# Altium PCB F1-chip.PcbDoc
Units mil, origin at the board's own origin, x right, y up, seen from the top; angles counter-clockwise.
Board outline 1181.1 x 1133.14 mil, 4 copper layers (Top Layer, GND, Signal & VCC, Bottom Layer), stack 23.756 mil thick; 61 components, 75 nets, 303 pads, 84 vias.
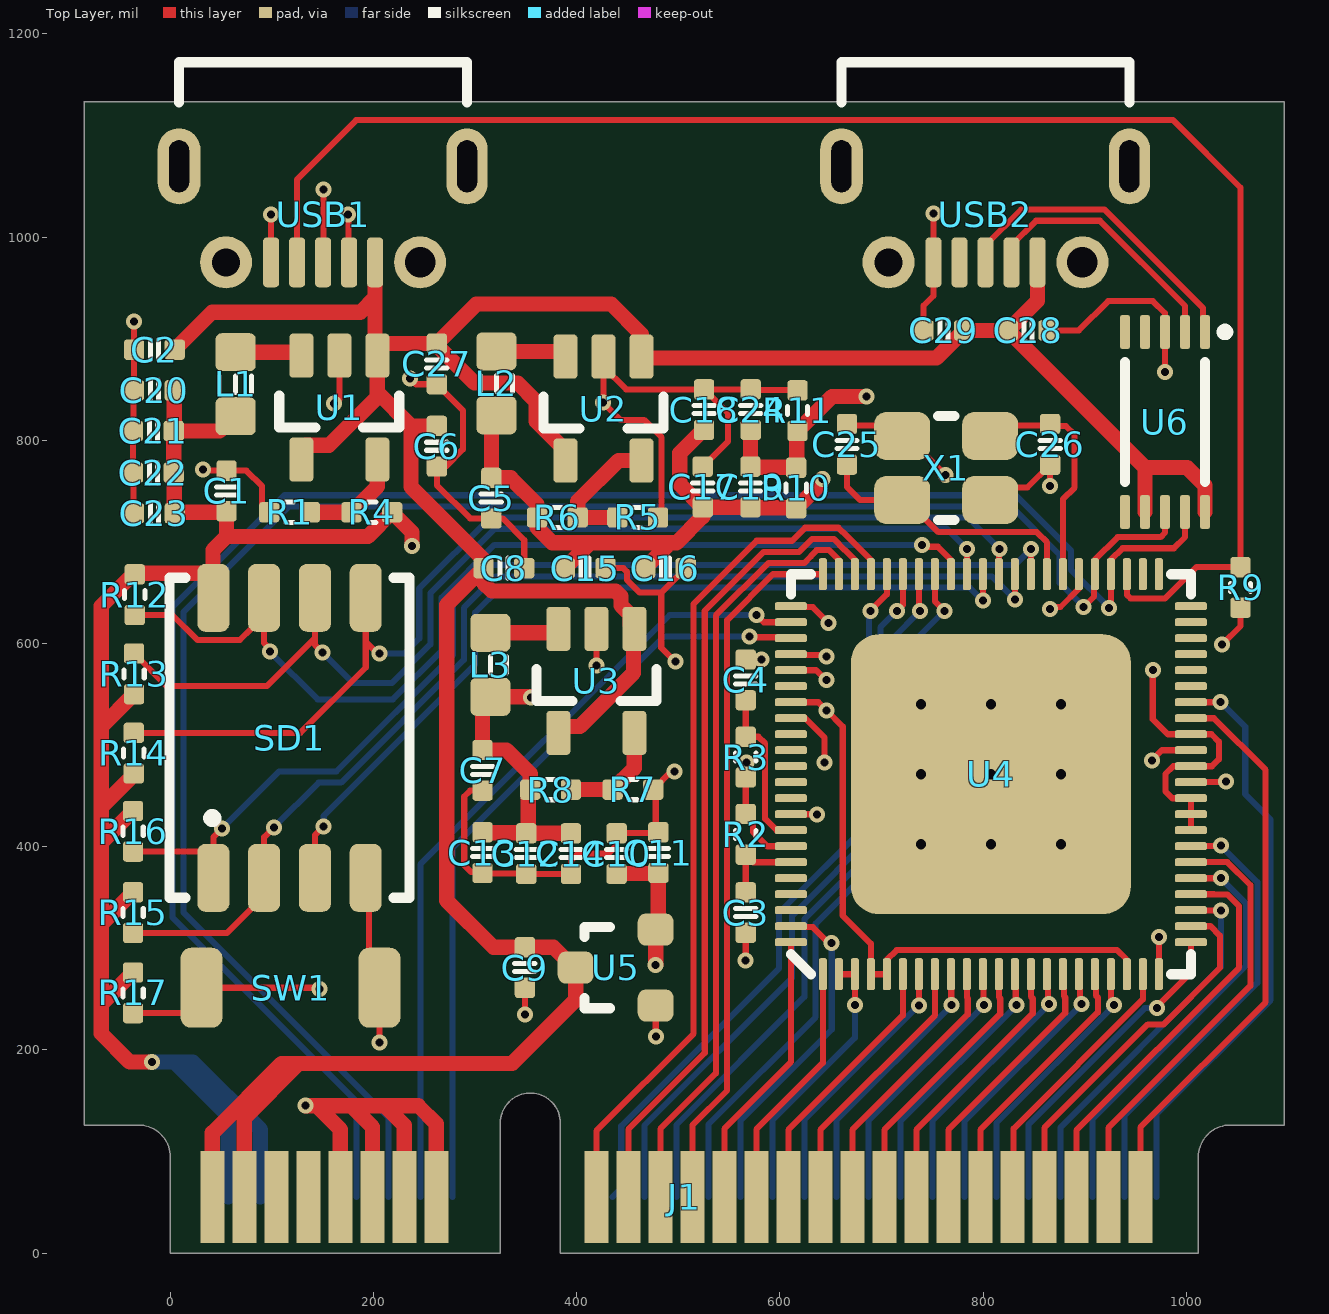
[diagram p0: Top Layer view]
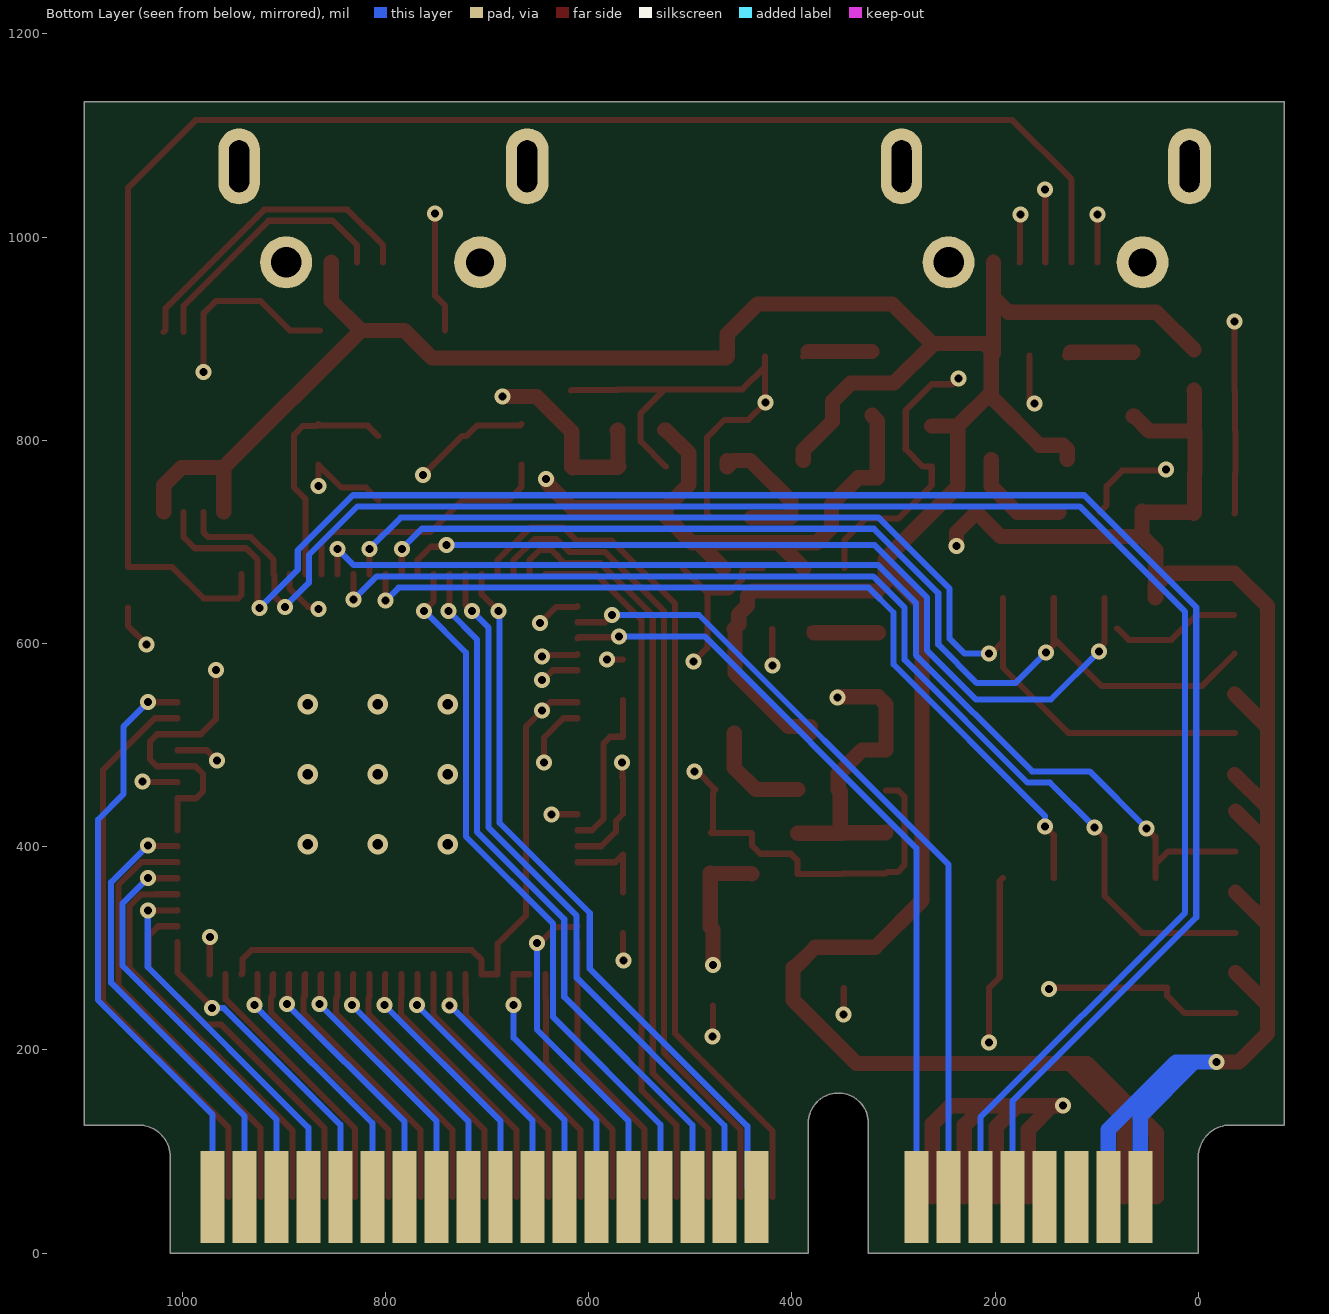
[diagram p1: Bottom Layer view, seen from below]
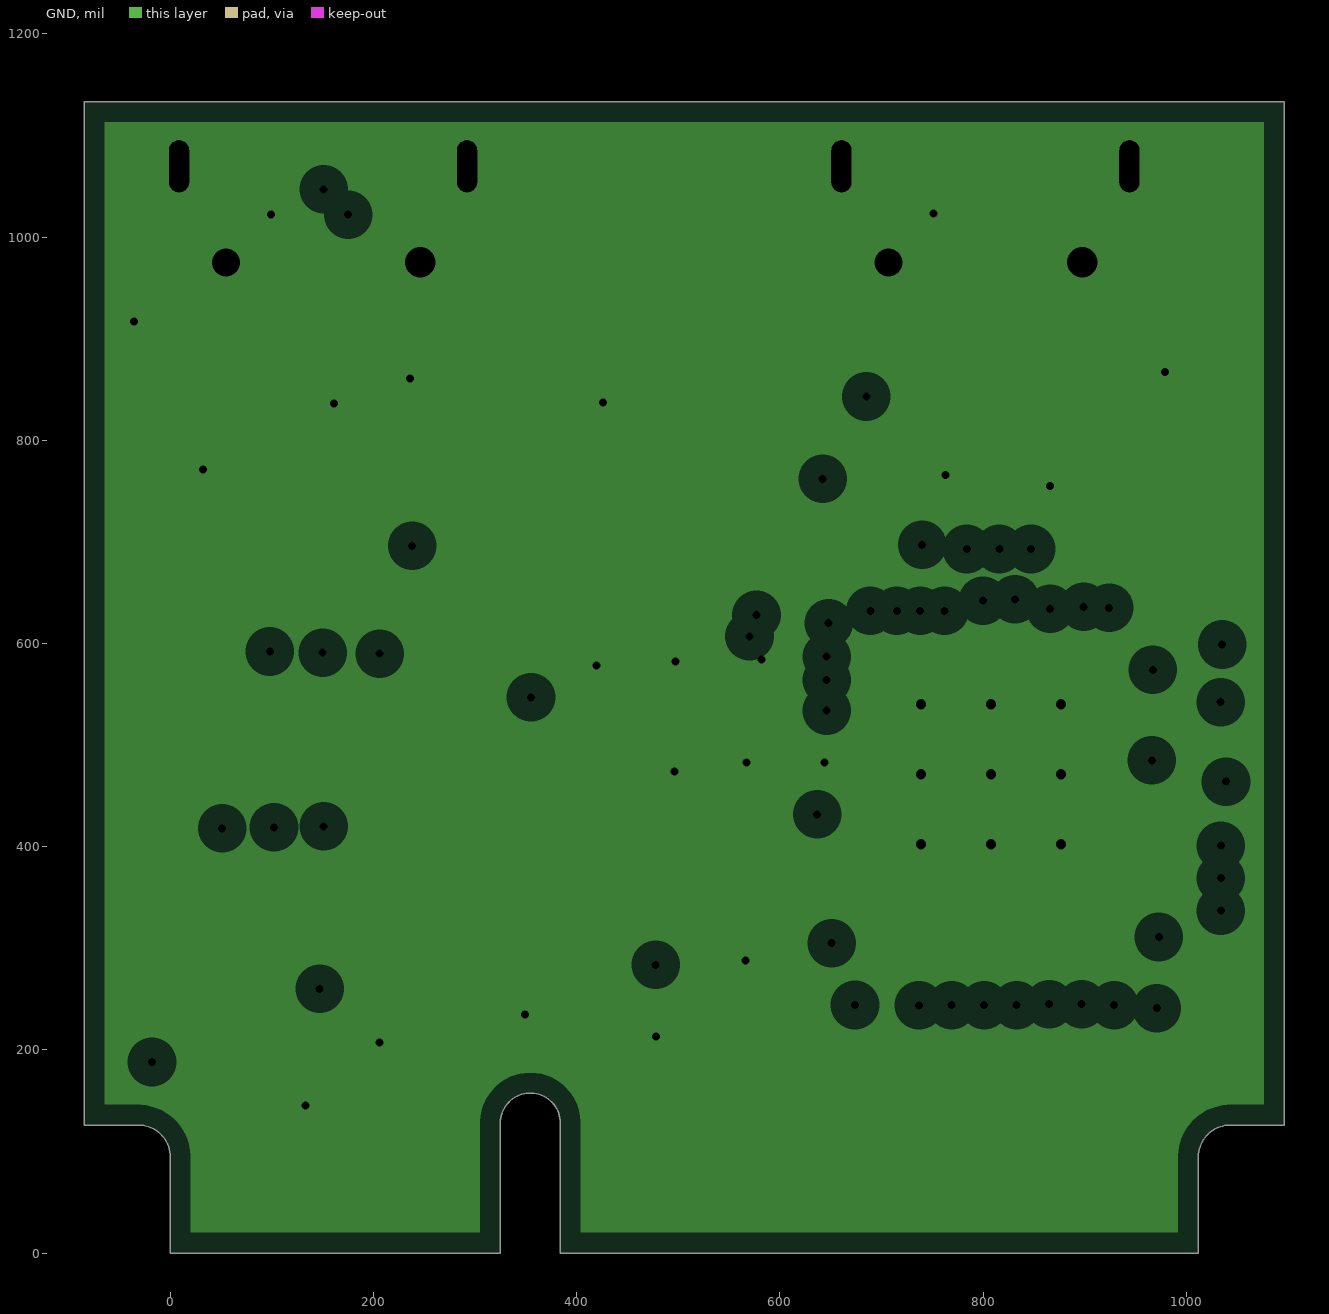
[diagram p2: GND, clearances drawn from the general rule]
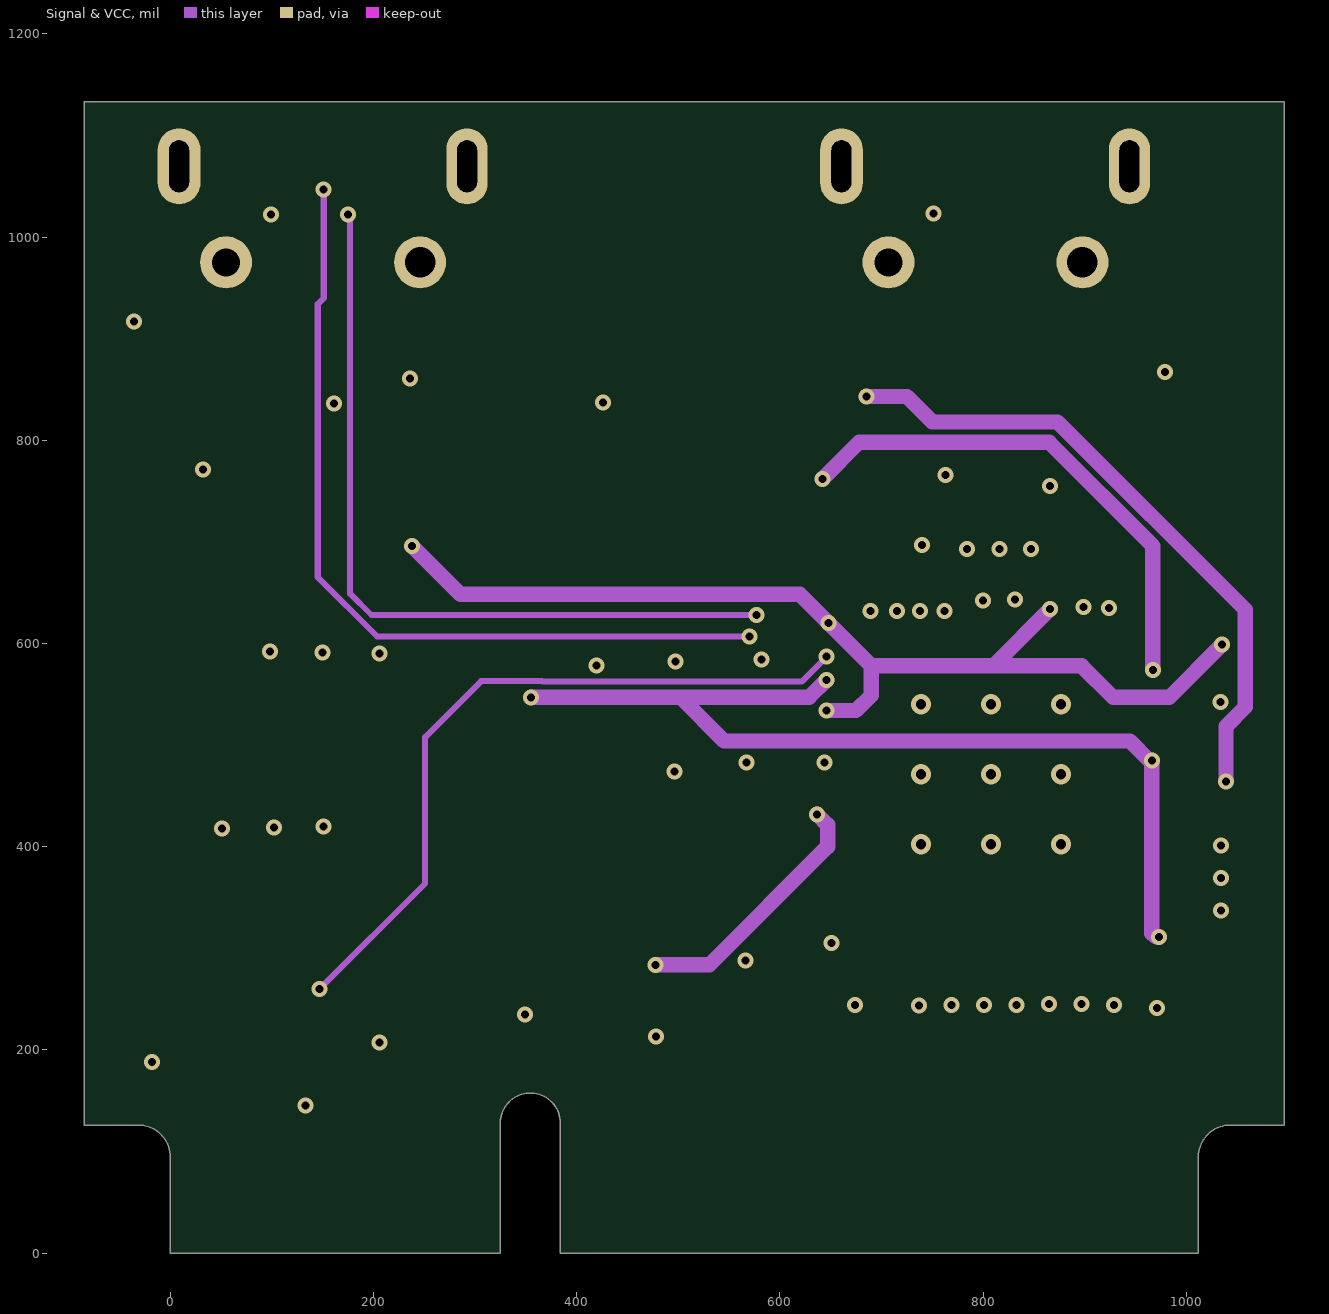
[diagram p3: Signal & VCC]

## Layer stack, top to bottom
Top Solder: solder mask 0.4, Solder Resist, Dk 3.5
Top Layer: signal copper 1.4
Dielectric 2: prepreg 2.8, PP-006, Dk 4.1
GND: plane copper 1.3778, net GND
Dielectric 1: dielectric 12.6, FR-4, Dk 4.8
Signal & VCC: signal copper 1.3778
Dielectric 3: prepreg 2.8, PP-006, Dk 4.1
Bottom Layer: signal copper 1.4
Bottom Solder: solder mask 0.4, Solder Resist, Dk 3.5

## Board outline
-31.5,125.98 cw(c-31.5,94.49) 0,94.49 0,0 324.8,0 324.8,127.95 cw(c354.33,127.95) 383.86,127.95 383.86,0 1011.81,0 1011.81,94.49 cw(c1043.31,94.49) 1043.31,125.98 1096.46,125.98 1096.46,1133.14 -84.65,1133.14 -84.65,125.98

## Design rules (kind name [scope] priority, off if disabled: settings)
Clearance [All] p1: gap=5 ignorepadtopadclearanceinfootprint=FALSE
DiffPairsRouting [All] p1: maxlimit=10 minlimit=3.5 mostfreqgap=3.5 toplayer_minwidth=3.5 toplayer_maxwidth=20 toplayer_prefwidth=15 midlayer1_minwidth=3.5 midlayer1_maxwidth=20 midlayer1_prefwidth=15 bottomlayer_minwidth=3.5 bottomlayer_maxwidth=20 bottomlayer_prefwidth=15 maxuncoupledlength=500
HoleSize [All] p1: absolutevalues=TRUE maxlimit=100 minlimit=7.87 maxpercent=80.000 minpercent=20.000
PlaneClearance [All] p1: clearance=20
PlaneConnect [All] p1: planeconnectstyle=Direct reliefexpansion=20 reliefentries=4 reliefconductorwidth=10 reliefairgap=10
PolygonConnect [All] p1: connectstyle=Relief reliefconductorwidth=10 reliefentries=4 polygonreliefangle="90 Angle" airgapwidth=10
RoutingVias [All] p1: holewidth=7.87 width=15.75 viastyle="Through Hole" minholewidth=7.87 minwidth=15.75 maxholewidth=28 maxwidth=50
SolderMaskExpansion [All] p1: expansion=1
Width [All] p1: maxlimit=20 minlimit=3.5 preferedwidth=6
26 further rules are at their usual default settings.

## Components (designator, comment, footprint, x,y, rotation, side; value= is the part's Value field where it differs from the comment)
C1 "10uF" CAP_0402 55.33,750.12 r90 top
C2 "10uF" CAP_0402 -15.67,889.12 r180 top
C3 "10uF" CAP_0402 566.33,335.12 r270 top
C4 "10uF" CAP_0402 566.33,564.12 r90 top
C5 "10uF" CAP_0402 316,743 r270 top
C6 "10uF" CAP_0402 262.33,794.12 r270 top
C7 "10uF" CAP_0402 307.33,475.12 r270 top
C8 "10uF" CAP_0402 328.33,674.12 r0 top
C9 "4.7uF" CAP_0402 349,281 r90 top
C10 "10uF" CAP_0402 439.33,393.12 r270 top
C11 "0.1uF" CAP_0402 480.33,394.12 r270 top
C12 "0.1uF" CAP_0402 350.33,393.12 r90 top
C13 "0.1uF" CAP_0402 307.33,394.12 r90 top
C14 "0.1uF" CAP_0402 394.33,393.12 r90 top
C15 "10uF" CAP_0402 408.33,674.12 r180 top
C16 "1uF" CAP_0402 487.33,674.12 r180 top
C17 "0.1uF" CAP_0402 524,754 r270 top
C18 "0.1uF" CAP_0402 525.33,830.12 r270 top
C19 "0.1uF" CAP_0402 571,754 r270 top
C20 "0.1uF" CAP_0402 -15.67,849.12 r0 top
C21 "0.1uF" CAP_0402 -16.67,809.12 r0 top
C22 "0.1uF" CAP_0402 -16.67,768.12 r0 top
C23 "0.1uF" CAP_0402 -15.67,728.12 r0 top
C24 "0.1uF" CAP_0402 571.33,830.12 r270 top
C25 "15pF" CAP_0402 666,796 r270 top
C26 "15pF" CAP_0402 866,796 r270 top
C27 "1uF" CAP_0402 262.33,875.12 r270 top
C28 "10uF" CAP_0402 844.33,908.12 r0 top
C29 "0.1uF" CAP_0402 761.33,908.12 r180 top
J1 "mini PCI-E" "mini PCI-E" 354.33,55.12 r0 top
L1 "2.2uH" IND_0603 64.33,855.12 r270 top
L2 "2.2uH" IND_0603 321,856 r270 top
L3 "2.2uH" IND_0603 315,579 r270 top
R1 "150K" RES_0402 117.33,729.12 r0 top
R2 "200K" RES_0402 566.33,412.12 r90 top
R3 "200K" RES_0402 566.33,488.12 r270 top
R4 "680K" RES_0402 198.33,729.12 r0 top
R5 "150K" RES_0402 460,724 r180 top
R6 "470K" RES_0402 381,724 r180 top
R7 "150K" RES_0402 455.33,456.12 r180 top
R8 "150K" RES_0402 374.33,456.12 r180 top
R9 "10K" RES_0402 1053.33,655.12 r90 top
R10 "2.2K" RES_0402 616,753 r270 top
R11 "2.2K" RES_0402 617.33,829.12 r270 top
R12 "10K" RES_0402 -35,648 r90 top
R13 "10K" RES_0402 -35.67,570.12 r270 top
R14 "10K" RES_0402 -36,492 r270 top
R15 "10K" RES_0402 -36.67,335.12 r90 top
R16 "10K" RES_0402 -36.67,415.12 r90 top
R17 "10K" RES_0402 -36.67,256.12 r90 top
SD1 "SD NAND" "SD NAND" 117.33,507.12 r90 top
SW1 "贴片按钮" BUTTON2 118.33,261.12 r180 top
U1 "SY8088AAC" SY8088AAC 166.33,832.12 r270 top
U2 "SY8088AAC" SY8088AAC 426.33,831.12 r270 top
U3 "SY8088AAC" SY8088AAC 419.33,563.12 r270 top
U4 "全志F1c200s" F1c200s 807.7,471.27 r90 top
U5 "XC6206-3.0V" XC6206 477.74,281 r270 top
U6 "CH340E" CH340E 979,818 r270 top
USB1 "MicroUSB" MicroUSB 150.33,975.12 r180 top
USB2 "MicroUSB" MicroUSB 802.33,975.12 r180 top
X1 "24MHz Crystal" SMD3225 763.64,772.62 r180 top

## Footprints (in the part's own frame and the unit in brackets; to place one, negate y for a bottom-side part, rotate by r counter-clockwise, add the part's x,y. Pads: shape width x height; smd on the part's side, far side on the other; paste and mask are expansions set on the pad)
BUTTON2 [mm] "3*4*2两脚小龟贴片按钮"
  rrect50% 1.05x2 smd mask+0.076: 1(-2.225,0) 2(2.225,0)
CAP_0402 [mil] "0402 Capacitor"
  rrect30% 20x20 smd mask+2.99: 1(-20,0) 2(20,0)
  silkscreen extent -4,-10 4,10
CH340E [mm] "MSOP-10"
  rrect50% 0.85x0.25 smd mask+0.076: 1(-2.25,1) 2(-2.25,0.5) 3(-2.25,0) 4(-2.25,-0.5) 5(-2.25,-1) 6(2.25,-1) 7(2.25,-0.5) 8(2.25,0) 9(2.25,0.5) 10(2.25,1)
  silkscreen extent -2.33,-1 1.5,1.58
F1c200s [mm] "QFN-88"
  rrect50% 0.8x0.2 smd mask+0.076: 1(-5,4.2) 2(-5,3.8) 3(-5,3.4) 4(-5,3) 5(-5,2.6) 6(-5,2.2) 7(-5,1.8) 8(-5,1.4) 9(-5,1) 10(-5,0.6) 11(-5,0.2) 12(-5,-0.2) 13(-5,-0.6) 14(-5,-1) 15(-5,-1.4) 16(-5,-1.8) 17(-5,-2.2) 18(-5,-2.6) 19(-5,-3) 20(-5,-3.4) 21(-5,-3.8) 22(-5,-4.2) 45(5,-4.2) 46(5,-3.8) 47(5,-3.4) 48(5,-3) 49(5,-2.6) 50(5,-2.2) 51(5,-1.8) 52(5,-1.4) 53(5,-1) 54(5,-0.6) 55(5,-0.2) 56(5,0.2) 57(5,0.6) 58(5,1) 59(5,1.4) 60(5,1.8) 61(5,2.2) 62(5,2.6) 63(5,3) 64(5,3.4) 65(5,3.8) 66(5,4.2)
  rrect50% 0.2x0.8 smd mask+0.076: 23(-4.2,-5) 24(-3.8,-5) 25(-3.4,-5) 26(-3,-5) 27(-2.6,-5) 28(-2.2,-5) 29(-1.8,-5) 30(-1.4,-5) 31(-1,-5) 32(-0.6,-5) 33(-0.2,-5) 34(0.2,-5) 35(0.6,-5) 36(1,-5) 37(1.4,-5) 38(1.8,-5) 39(2.2,-5) 40(2.6,-5) 41(3,-5) 42(3.4,-5) 43(3.8,-5) 44(4.2,-5) 67(4.2,5) 68(3.8,5) 69(3.4,5) 70(3,5) 71(2.6,5) 72(2.2,5) 73(1.8,5) 74(1.4,5) 75(1,5) 76(0.6,5) 77(0.2,5) 78(-0.2,5) 79(-0.6,5) 80(-1,5) 81(-1.4,5) 82(-1.8,5) 83(-2.2,5) 84(-2.6,5) 85(-3,5) 86(-3.4,5) 87(-3.8,5) 88(-4.2,5)
  rrect20% 7x7 smd mask+0.076: 89(0,0)
  silkscreen extent -5,-5 5,5
IND_0603 [mm] "0603 Inductor"
  rrect30% 0.95x1 smd mask+0.076: 1(-0.8,0) 2(0.8,0)
  silkscreen extent -0.2,-0.4 0.2,0.4
MicroUSB [mm] "MicroUSB"
  oval 1.03x1.9 hole 1.3 slot 0.5 at 0 deg mask+0.076: 0(-3.6,-2.4)
  round 1.3 hole 0.762 mask+0.076: 0(-2.425,0)
  round 1.3 hole 0.7 mask+0.076: 0(2.425,0)
  oval 1.07x1.9 hole 1.3 slot 0.5 at 0 deg mask+0.076: 0(3.6,-2.4)
  rrect50% 0.4x1.25 smd mask+0.076: 1(-1.3,0) 2(-0.65,0) 3(0,0) 4(0.65,0) 5(1.3,0)
  silkscreen extent -3.6,-5 3.6,-4
"mini PCI-E" [mm] "mini PCI-E"
  rect 0.6x2.3 smd mask+0.076: 1(-7.95,0) 3(-7.15,0) 5(-6.35,0) 7(-5.55,0) 9(-4.75,0) 11(-3.95,0) 13(-3.15,0) 15(-2.35,0) 17(1.65,0) 19(2.45,0) 21(3.25,0) 23(4.05,0) 25(4.85,0) 27(5.65,0) 29(6.45,0) 31(7.25,0) 33(8.05,0) 35(8.85,0) 37(9.65,0) 39(10.45,0) 41(11.25,0) 43(12.05,0) 45(12.85,0) 47(13.65,0) 49(14.45,0) 51(15.25,0)
  rect 0.6x2.3 smd far side mask+0.076: 2(-7.55,0) 4(-6.75,0) 6(-5.95,0) 8(-5.15,0) 10(-4.35,0) 12(-3.55,0) 14(-2.75,0) 16(-1.95,0) 16(-1.95,0) 18(2.05,0) 18(2.05,0) 20(2.85,0) 22(3.65,0) 24(4.45,0) 26(5.25,0) 28(6.05,0) 30(6.85,0) 32(7.65,0) 34(8.45,0) 36(9.25,0) 38(10.05,0) 40(10.85,0) 42(11.65,0) 44(12.45,0) 46(13.25,0) 48(14.05,0) 50(14.85,0) 52(15.65,0)
RES_0402 [mil] "0402 Resistor"
  rrect30% 20x20 smd mask+2.99: 1(-20,0) 2(20,0)
  silkscreen extent -4,-10 4,10
"SD NAND" [mm] "SD NAND"
  rrect50% 1.7x0.8 smd mask+0.076: 1(-3.5,1.905) 1(-3.5,1.905) 2(-3.5,0.635) 3(-3.5,-0.635) 4(-3.5,-1.905) 5(3.5,-1.905) 5(3.5,-1.905) 6(3.5,-0.635) 7(3.5,0.635) 8(3.5,1.905)
  silkscreen extent -4,-3 4,3
SMD3225 [mm] "SMD3225 Crystal"
  rrect50% 1.4x1.2 smd mask+0.076: 1(-1.1,-0.8) 2(1.1,-0.8) 3(1.1,0.8) 4(-1.1,0.8)
  silkscreen extent -0.2,-1.3 0.2,1.3
SY8088AAC [mm] "SY8088AAC"
  rrect30% 1.1x0.6 smd mask+0.07: 1(-1.3,0.95) 2(-1.3,0) 3(-1.3,-0.95) 4(1.3,-0.95) 5(1.3,0.95)
  silkscreen extent -0.3,-1.5 0.5,1.5
XC6206 [mm] "SOT23"
  rrect50% 0.8x0.9 smd: 1(0.95,0) 2(-0.95,0) 3(0,-2)
  silkscreen extent -1.02,-1.78 1.02,-1.14

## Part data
C1 C2 C3 C4 C5 C6 C7 C8 C10 C15 C28: library part CAP_0402_10uF, "0402"
C9: library part CAP_0402_4.7uF, "0402"
C11 C12 C13 C14 C17 C18 C19 C20 C21 C22 C23 C24 C29: library part CAP_0402_0.1uF, "0402"
C16 C27: library part CAP_0402_1uF, "0402"
C25 C26: library part CAP_0402_15pF, "0402"
L1 L2 L3: library part IND_0603_2.2uH, "0603"
R1 R5 R7 R8: library part RES_0402_150K, "0402"
R2 R3: library part RES_0402_200K, "0402"
R4: library part RES_0402_680K, "0402"
R6: library part RES_0402_470K, "0402"
R9 R12 R13 R14 R15 R16 R17: library part RES_0402_10K, "0402"
R10 R11: library part RES_0402_2.2K, "0402"
SW1: "3*4*2两脚小龟贴片按钮"
U1 U2 U3: "SOT23-5"
U4: library part F1c200s, "MQFN-88"
U5: "SOT23-3"
U6: "MSOP-10"
X1: "SMD3225"

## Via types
v1: diameter 15.75, hole 7.87, Top Layer to Bottom Layer, 75 vias
v2: diameter 20, hole 10, Top Layer to Bottom Layer, tented both sides, 9 vias

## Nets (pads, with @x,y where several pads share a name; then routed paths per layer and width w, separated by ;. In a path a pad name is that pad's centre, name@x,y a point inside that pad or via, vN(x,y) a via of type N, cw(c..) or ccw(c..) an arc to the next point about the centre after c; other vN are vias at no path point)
5VIN: C2.1 C6.1 C8.1 C9.2 C27.1 C28.1 C29.1 J1.1 J1.3 U1.1 U1.4 U2.1 U2.4 U3.1 U3.4 U5.3 U6.7 U6.10 USB1.1 USB2.1 | length 3479.8
  Top Layer w15: C2.1 41.21,926 187,926 201.51,940.51 ; J1.1 41.34,118.34 109.44,186.44 126.44,186.44 ; J1.3 72.83,132.83 126.44,186.44 ; U1.4 128.93,790.78 133.24,795.09 156.09,795.09 203.73,842.73 203.73,847.27 ; USB1.1 201.51,941 201.51,940.51 ; U1.1@203.73,888.31 210.54,895.12 C27.1 ; C6.1 236.88,814.12 ; U3.4 381.93,518.28 403.28,518.28 456,571 456,613.57 U3.1 452.42,618.61 452.42,628.45 443.64,637.23 443.64,646.33 438.35,651.62 316.38,651.62 308.33,659.67 C8.1 ; U2.4 388.93,789.78 360,818.71 360,838.28 341.99,856.3 299.42,856.3 262.33,893.39 C27.1 ; USB2.1 853.51,937.3 C28.1 ; U6.7 959.31,773.13 ; U6.10 1018.37,755.63 1000.87,773.13 959.31,773.13 ; 126.44,186.44 336.44,186.44 399,249 U5.3 397.03,281 377.03,301 C9.2 318,301 272,347 272,637.79 C8.1 ; 201.51,940.51 201.51,885.52 U1.1 203.73,847.27 ; 203.73,847.27 236.88,814.12 ; 236.88,814.12 236.88,754.12 308.33,682.67 C8.1 ; C27.1 301.21,934 434,934 463.73,904.27 U2.1 465.03,881 754.21,881 C29.1 C28.1 ; C28.1 959.31,773.13
+1V1: C7.1 C12.2 C13.2 C14.2 L3.2 R8.2 U4.22 U4.35 U4.71 | length 1384.9
  Top Layer w6: U4.71 635.6,573.63 645.23,564 v1(646,564) ; v1(966,485) 975.89,494.89 U4.35 ; U4.22 v1(973,311)
  Top Layer w15: C13.2 307.83,413.62 C12.2@349.83,413.62 ; v1(355,547) 354.5,547.5 L3.2 307.33,539.83 C7.1 330.88,495.12 354.33,471.67 R8.2 352.33,454.12 352.33,416.12 C12.2@349.83,413.62 ; C14.2 C12.2 C12.2@349.83,413.62
  Signal & VCC w15: v1(355,547) 355.04,546.96 432.33,546.96 432.37,547 502,547 ; v1(646,564) 645.8,564 628.8,547 502,547 ; v1(973,311) 970.36,311 966.85,314.51 966,314.51 v1(966,485) 963.36,485 944.36,504 545,504 502,547
+2V5: C5.1 C15.2 C16.2 C17.2 C18.2 C19.2 L2.2 R6.2 R10.2 U4.30 U4.31 U4.32 U4.34 U4.36 | length 1407.4
  Top Layer w6: v1(967,574) 967,525.41 981.78,510.64 1024.77,510.64 1032,503.41 1032,486 1025.14,479.14 U4.34 987.14,479.14 979.49,471.49 979.49,454.51 986.35,447.65 U4.32 U4.31 U4.30
  Top Layer w15: L2.2 316,819.5 C5.1 335,763 361,737 R6.2 361,714 376,699 413.21,699 ; C15.2 413.21,699 ; C16.2 488,694.79 488,699 ; C18.2 524.2,810.12 501.5,787.42 501.5,756.5 C17.2 ; v1(642,762) 640.13,760.13 640.13,757.13 R10.2 615.5,733.5 571.5,733.5 C19.2 C17.2 ; 413.21,699 488,699 ; 488,699 498.21,699 524,724.79 C17.2
  Signal & VCC w15: v1(642,762) 678,798 865,798 967,696 v1(967,574)
+3V0: C10.2 C11.2 U4.80 U5.2 | length 412.2
  Top Layer w6: U4.80 636.6,431.9 v1(636.72,431.78)
  Top Layer w15: C10.2 439.83,373.62 479.83,373.62 C11.2 480.33,320.99 U5.2 v1(477.74,283.74)
  Signal & VCC w15: v1(477.74,283.74) 530.74,283.74 647,400 647,421.5 v1(636.72,431.78)
+3V3: C1.1 C20.2 C21.2 C22.2 C23.2 J1.2 J1.4 L1.2 R4.2 R9.1 R12.2 R13.2 R14.2 R15.2 R16.2 R17.2 SD1.8 U4.4 U4.5 U4.20 U4.50 U4.67 U4.73 | length 3527.3
  Top Layer w6: U4.73 637.87,542.13 v1(646,534) 661.87,518.13 661.87,332.13 689.59,304.41 U4.4 U4.5 705.34,288.52 714.99,298.17 931.91,298.17 940.62,289.45 940.62,275.36 U4.20 ; U4.67 611.79,635.69 632.31,635.69 v1(648,620) ; v1(866,634) 867.87,635.87 876.16,635.87 894.31,654.02 U4.50 ; v1(1035.24,599) 1053.33,617.09 R9.1
  Top Layer w15: -67.89,438.89 R14.2@-35.67,471.12 ; -67.39,324.39 R15.2 ; -66.89,404.89 R16.2 ; R17.2 -67.79,245 -68,245 ; R13.2 -68,517.79 ; v1(-18,188) -40,188 -68,216 -68,245 ; C20.2 3.83,848.62 3.83,809.62 C21.2 ; L1.2 63.02,823.62 48.51,809.12 C21.2 ; v1(238,696) 238,709.45 R4.2 194.54,705.33 55.33,705.33 ; -68,245 -68,517.79 ; -68,517.79 -68,636.79 -35.67,669.12 29.95,669.12 SD1.8@42,657.07 ; C21.2 C22.2 3.83,767.62 3.83,728.62 C23.2 5.33,729.12 54.33,729.12 C1.1 55.33,705.33 ; SD1.8@42,657.07 42.33,656.74 SD1.8 42,645.24 SD1.8@42,657.07 ; SD1.8@42,657.07 42,692 55.33,705.33
  Signal & VCC w15: v1(238,696) 285.63,648.37 619.63,648.37 v1(648,620) 690,578 ; v1(646,534) 675,534 690,549 690,578 ; v1(866,634) 810,578 ; v1(1035.24,599) 983.24,547 928,547 897,578 810,578 ; 690,578 810,578
  Bottom Layer w15: v1(-18,188) 4,188 ; J1.2 57.09,134.91 4,188 ; J1.4 88.58,121.42 22,188 4,188
D+: U6.1 USB2.3 | length 309.9
  Top Layer w6: USB2.3 802.33,991.85 837.48,1027 919.56,1027 1016.45,930.11 1016.45,908.5 U6.1
D-: U6.2 USB2.2 | length 257.9
  Top Layer w6: USB2.2 827.92,991.85 852.07,1016 915,1016 998.68,932.31 U6.2
DRAM_VREF_33: C19.1 C24.2 R10.1 R11.2 U4.33 | length 873.2
  Top Layer w6: U4.33 1004.85,463.7 1038.7,463.7 v1(1039,464)
  Top Layer w15: C19.1@570.5,774.5 C19.1 ; C24.2@571.83,809.62 C24.2 571.17,809.95 571.17,774.17 C19.1 ; v1(685,843) 651.21,843 R11.2 616.67,808.45 616.67,773.67 R10.1 615.5,773.5 571.5,773.5 C19.1
  Signal & VCC w15: v1(685,843) 725,843 750,818 873.28,818 1058,633.28 1058,537.46 1039,518.46 v1(1039,464)
GND: C1.2 C2.2 C3.2 C4.2 C5.2 C6.2 C7.2 C8.2 C9.1 C10.1 C11.1 C12.1 C13.1 C14.1 C15.1 C16.1 C17.1 C18.1 C20.1 C21.1 C22.1 C23.1 C24.1 C25.1 C26.2 C27.2 C28.2 C29.2 J1.9 J1.11 J1.13 J1.15 R1.1 R2.2 R3.2 R5.1 R7.1 R11.1 SD1.4 SW1.1 U1.2 U2.2 U3.2 U4.74 U4.82 U4.89 U5.1 U6.3 USB1.0 USB1.5 USB2.0 USB2.5 X1.2 X1.4 | length 3239
  Top Layer w6: C23.1 -36.17,728.62 -36.17,767.62 C22.1 C21.1 -36.17,809.62 -36.17,848.62 C20.1 C2.2 v1(-35.67,916.67) ; v1(32,771) 32.88,770.12 C1.2 74.88,770.12 90.33,754.67 90.33,736.12 R1.1 ; USB1.5 v1(99.15,1022.15) ; v1(161,836) 162,836 166.33,840.33 U1.2 ; SD1.4 195.46,366.19 195.46,271.58 SW1.1 206,261.05 v1(206,207) ; v1(236,861) 241.88,855.12 C27.2 288,829.45 288,791 271.12,774.12 C6.2 262.33,755.67 295,723 C5.2 327,723 348.33,701.67 C8.2 ; C7.2 295.12,455.12 289.33,449.33 289.33,381.67 296,375 306.45,375 C13.1 307.83,373.62 349.83,373.62 C12.1 C14.1 394.33,386.33 401,393 431,393 439.33,401.33 C10.1 439.83,413.62 479.83,413.62 477.83,415.62 477.83,453.62 R7.1 493.21,474 v1(496,474) ; v1(349,235) C9.1 ; v1(419.33,578.33) U3.2 ; U2.2 U2.2@426.33,872.46 ; C15.1 445.82,674.12 449.33,670.6 449.33,662.56 461.89,650 483.21,650 ; U5.1 477.74,213.26 v1(478,213) ; R5.1 483.54,727.54 483.54,802.83 466.37,820 443,820 v1(426,837) 426.33,837.33 U2.2@426.33,872.46 ; v1(497,582) 483.21,595.79 483.21,650 ; C16.1 483.21,650 ; C17.1 549,799 549,826.45 C18.1 ; v1(566,288) 566.33,288.33 C3.2 ; C4.2 566.39,584.06 581.94,584.06 v1(582,584) ; v1(567,483) 566.67,482.67 566.67,469.12 567,468.79 R3.2 R2.2 573.33,425.12 573.33,414.67 587.6,400.4 U4.82 ; U4.74 624.95,526.39 644,507.33 v1(644,483) v1@643,483 ; R11.1 616.83,849.62 571.83,849.62 C24.1 C18.1 ; C25.1 667.54,814.46 709.98,814.46 X1.2 724.88,804.12 724.88,803.81 762.69,766 v1(763,766) ; C29.2 741.33,932.33 751.15,942.15 USB2.5 v1(751.15,1023.15) ; X1.4 819.32,753.5 843.5,753.5 C26.2 v1(866,755) ; C28.2 894.12,908.12 923,937 967,937 979,925 U6.3 v1(979,867) ; U2.2@426.33,872.46 448.67,850.12 C18.1
  Top Layer w15: v1(133,145) 144,145 ; J1.9 167.32,121.68 144,145 ; J1.11 199,55.3 199,124 178,145 ; J1.13 230.31,125.69 211,145 ; J1.15 261.81,127.19 244,145 211,145 ; 144,145 178,145 ; 178,145 211,145
  other v2: 738.8,402.37 807.7,402.37 876.6,402.37 738.8,471.27 807.7,471.27 876.6,471.27 738.8,540.17 807.7,540.17 876.6,540.17
HOSCI: C26.1 U4.51 X1.1 | length 234.4
  Top Layer w6: X1.1 817.29,814.46 864.47,814.46 C26.1 868,814 881.49,814 890,805.49 890,753.42 878.57,741.99 U4.51
HOSCO: C25.2 U4.52 X1.3 | length 273
  Top Layer w6: C25.2 666,754 678.87,741.13 724.27,741.13 755.89,709.5 852.95,709.5 862.94,699.5 862.94,668.24 U4.52
HPCOM: J1.28 U4.2 U4.3 | length 268.7
  Top Layer w6: U4.2 U4.3 v1(673.84,244.16)
  Bottom Layer w6: J1.28 592.52,130.52 673.84,211.84 v1(673.84,244.16)
HPL: J1.27 U4.1 | length 246.5
  Top Layer w6: J1.27 576.77,121.77 642.22,187.22 642.22,250.67 642.35,250.8 U4.1
HPR: J1.25 U4.88 | length 278
  Top Layer w6: J1.25 545.27,122.27 610.85,187.85 U4.88
I2C_CL: J1.52 U4.38 | length 583.3
  Top Layer w6: U4.38 v1(1033.87,542.13)
  Bottom Layer w6: J1.52 970.47,136.47 1083,249 1083,426.68 1058,451.68 1058,518 v1(1033.87,542.13)
I2C_DA: J1.51 U4.37 | length 566
  Top Layer w6: J1.51 954.72,123.72 1078,247 1078,475.55 1027.16,526.39 U4.37
MICIN: J1.26 U4.87 | length 334.2
  Top Layer w6: U4.87 611.79,320.73 632.27,320.73 648,305 v1(651,305)
  Bottom Layer w6: J1.26 561.02,130.02 651,220 v1(651,305)
NetC3_1: C3.1 R2.1 U4.83 | length 84.6
  Top Layer w6: C3.1 R2.1 573.79,384.65 U4.83
NetC4_1: C4.1 R3.1 U4.81 | length 162
  Top Layer w6: C4.1 R3.1 578.88,508.12 585.41,501.59 585.41,427.49 596.75,416.15 U4.81
NetL1_1: L1.1 U1.3 | length 66
  Top Layer w10: U1.3@125.61,886.61 U1.3
  Top Layer w15: L1.1 U1.3@125.61,886.61
NetL2_1: L2.1 U2.3 | length 70.1
  Top Layer w6: L2.1 L2.1@321.09,887.41 ; U2.3@383.82,887.41 U2.3
  Top Layer w15: L2.1@321.09,887.41 U2.3@383.82,887.41
NetL3_1: L3.1 U3.3 | length 68.5
  Top Layer w6: U3.3@378.13,610.5 U3.3
  Top Layer w15: L3.1 U3.3@378.13,610.5
NetR1_2: R1.2 R4.1 U1.5 | length 103.3
  Top Layer w15: R1.2 R4.1 203.73,754.52 U1.5
NetR5_2: R5.2 R6.1 U2.5 | length 143.3
  Top Layer w15: R5.2 R6.1 401,740 441,780 457.33,780 463.73,773.6 U2.5
NetR7_2: R7.2 R8.1 U3.5 | length 105.7
  Top Layer w15: R8.1 R7.2 456.73,477.52 U3.5
PD0: J1.29 U4.6 | length 266
  Top Layer w6: J1.29 608.27,121.27 720.96,233.96 720.96,252.74 721.09,252.87 U4.6
PD1: J1.30 U4.7 | length 266
  Top Layer w6: v1(736.83,243.83) U4.7
  Bottom Layer w6: J1.30 624.02,131.02 v1(736.83,243.83)
PD2: J1.31 U4.8 | length 266.1
  Top Layer w6: J1.31 639.76,121.27 752.71,234.21 752.71,250.41 752.58,250.54 U4.8
PD3: J1.32 U4.9 | length 266.6
  Top Layer w6: U4.9 768.67,274.08 768.67,244.33 v1(769,244)
  Bottom Layer w6: J1.32 655.51,130.51 v1(769,244)
PD4: J1.33 U4.10 | length 266.7
  Top Layer w6: J1.33 671.26,121.27 784.87,234.88 784.87,250.58 784.08,251.37 U4.10
PD5: J1.34 U4.11 | length 269.8
  Top Layer w6: v1@799,242 v1(801,244) 800.41,244.59 800.41,273.83 U4.11
  Bottom Layer w6: J1.34 687.01,130.01 v1(801,244)
PD6: J1.35 U4.12 | length 267.1
  Top Layer w6: J1.35 702.76,121.27 816.87,235.39 816.87,250.58 815.57,251.87 U4.12
PD7: J1.36 U4.13 | length 267.4
  Top Layer w6: U4.13 832.16,273.58 832.16,244.84 v1(833,244)
  Bottom Layer w6: J1.36 718.5,129.5 v1(833,244)
PD8: J1.37 U4.14 | length 267.5
  Top Layer w6: J1.37 734.25,121.27 848.87,235.89 848.87,250.58 847.07,252.38 U4.14
PD9: J1.38 U4.15 | length 267.8
  Top Layer w6: U4.15 863.76,273.48 863.76,246.24 v1(865,245)
  Bottom Layer w6: J1.38 750,130 v1(865,245)
PD10: J1.39 U4.16 | length 267.9
  Top Layer w6: J1.39 765.75,121.27 880.87,236.39 880.87,251.58 879.5,252.95 879.5,273.48 U4.16
PD11: J1.40 U4.17 | length 271.3
  Top Layer w6: U4.17 895.25,273.48 895.25,246.75 v1(897,245) v1@897,242
  Bottom Layer w6: J1.40 781.5,129.5 v1(897,245)
PD12: J1.41 U4.18 | length 268.4
  Top Layer w6: J1.41 797.24,121.27 912.87,236.9 912.87,251.58 911,253.45 911,273.48 U4.18
PD13: J1.42 U4.19 | length 269.7
  Top Layer w6: U4.19 925.97,274.26 925.97,249.67 929,246.64 v1(929,244) v1@929,243
  Bottom Layer w6: J1.42 812.99,127.99 v1(929,244)
PD14: J1.43 U4.21 | length 272
  Top Layer w6: J1.43@830,55.12 830,122.45 957.31,249.76 U4.21
PD15: J1.44 U4.23 | length 324.1
  Top Layer w6: v1(971,241) 971,242.52 1004.55,276.07 U4.23
  Bottom Layer w6: J1.44 844.49,126.49 959,241 v1(971,241)
PD16: J1.45 U4.24 | length 370.2
  Top Layer w6: J1.45 860.24,123.24 962.13,225.13 977.58,225.13 1033,280.55 1033,312.49 1023.82,321.66 U4.24
PD17: J1.46 U4.25 | length 377
  Top Layer w6: U4.25 1004.76,337.21 1033.79,337.21 v1(1034,337)
  Bottom Layer w6: J1.46 875.98,123.54 1034,281.55 v1(1034,337)
PD18: J1.47 U4.26 | length 405
  Top Layer w6: J1.47 891.73,120.73 1052,281 1052,341.45 1040.42,353.03 1027.33,353.03 1027.2,353.16 U4.26
PD19: J1.48 U4.27 | length 416.3
  Top Layer w6: U4.27 v1(1033.91,368.91)
  Bottom Layer w6: J1.48 907.48,131.48 1059,283 1059,343.81 v1(1033.91,368.91)
PD20: J1.49 U4.28 | length 432.9
  Top Layer w6: J1.49 923.23,123.23 1063,263 1063,362.26 1040.48,384.78 1004.68,384.78 U4.28
PD21: J1.50 U4.29 | length 444.8
  Top Layer w6: U4.29 1004.85,400.7 1033.7,400.7 v1(1034,401)
  Bottom Layer w6: J1.50 938.98,134.98 1070,266 1070,365 v1(1034,401)
PE3: U4.46
PE4: U4.45
PE5: U4.44
PE6: U4.43
PE7: U4.42
PE8: U4.41
PE9: U4.40
PE10: U4.39
RESET: R17.1 SW1.2 U4.70 | length 954.4
  Top Layer w6: R17.1 13.62,236.12 30.73,253.23 SW1.2 145.88,261.12 v1(147,260) ; U4.70 611.79,588.44 644.56,588.44 v1(646,587)
  Signal & VCC w6: v1(147,260) 250.71,363.71 250.71,507.71 305.87,562.87 365.68,562.87 366.1,562.46 425.91,562.46 425.95,562.5 621.5,562.5 v1(646,587)
RXD: J1.12 U4.49 U6.8 | length 1796.7
  Top Layer w6: v1(899,636) 909.13,646.13 909.13,667.18 U4.49 910.06,682.22 932.53,704.68 974.68,704.68 979,709 U6.8
  Bottom Layer w6: J1.12 214.57,133.43 13,335 13,631 116.87,734.87 827.58,734.87 875.39,687.06 875.39,659.61 v1(899,636)
SDC0_CLK: SD1.3 U4.56 | length 869
  Top Layer w6: SD1.3 142.33,411.33 v1(151,420) ; U4.56 v1(799.83,642.17) v1@801.17,642.17
  Bottom Layer w6: v1(151,420) 151,430.33 300,579.33 300,630.44 324.56,655 787,655 v1(799.83,642.17)
SDC0_CMD: R14.1 SD1.5 U4.55 | length 1091.8
  Top Layer w6: R14.1 128,512 192.33,576.33 192.33,644.91 SD1.5@192.33,627.2 ; 192.33,601.67 204,590 v1(206,590) ; U4.55 815.79,668.33 815.79,692.79 v1(816,693)
  Bottom Layer w6: v1(206,590) 230,590 245,605 245,654.11 314.76,723.87 785.13,723.87 v1(816,693)
SDC0_D0: R13.1 SD1.6 U4.57 | length 1040.1
  Top Layer w6: R13.1 -3.55,558 95,558 142.33,605.33 ; SD1.6 142.33,605.33 ; v1(150,591) 142.33,598.67 142.33,605.33 ; v1(784,693) 784.04,692.96 U4.57 U4.57
  Bottom Layer w6: v1(150,591) 180,561 218,561 256,599 256,649.56 319.32,712.87 764.13,712.87 v1(784,693)
SDC0_D1: R12.1 SD1.7 U4.58 | length 988.6
  Top Layer w6: R12.1 2.11,628 26.66,603.45 68.58,603.45 SD1.7@80,614.87 ; SD1.7 92.33,600.31 98,594.64 v1(98,592) ; v1(740,697) 741.87,695.13 755.41,695.13 768.33,682.22 U4.58
  Bottom Layer w6: v1(98,592) 145,545 219,545 267,593 267,645 319,697 v1(740,697)
SDC0_D2: R16.1 SD1.1 U4.53 | length 1101.4
  Top Layer w6: R16.1 29.95,395.12 SD1.1@42.33,382.74 ; SD1.1@42.33,369.32 SD1.1@42.33,382.74 ; v1(51,418) 42.33,409.33 SD1.1@42.33,382.74 ; U4.53 v1(847.07,692.93)
  Bottom Layer w6: v1(51,418) 107,474 163.56,474 278,588.44 278,640 315.13,677.13 831.27,677.13 v1(847.07,692.93)
SDC0_D3: R15.1 SD1.2 U4.54 | length 1111.3
  Top Layer w6: R15.1 55.84,315.12 92.33,351.61 SD1.2 92.33,409.33 v1(102,419) ; v1(831.32,643.32) U4.54
  Bottom Layer w6: v1(102,419) 146,463 168.11,463 289,583.89 289,635 320,666 808.65,666 v1(831.32,643.32)
SPI0_CLK: J1.24 U4.59 | length 713.2
  Top Layer w6: U4.59 752.58,641.42 v1(762,632)
  Bottom Layer w6: J1.24 529.53,126.53 635.13,232.13 635.13,324.15 720.8,409.83 720.8,590.8 v1(762,632)
SPI0_CS: J1.22 U4.60 | length 714.2
  Top Layer w6: U4.60@737.77,667.18 U4.60 736.83,633.17 v1(738,632)
  Bottom Layer w6: J1.22 498.03,126.03 624.13,252.13 624.13,328.71 709.8,414.38 709.8,603.8 v1(738,632)
SPI0_MISO: J1.20 U4.61 | length 718.4
  Top Layer w6: v1(715,632) 721.09,638.09 U4.61
  Bottom Layer w6: J1.20 466.53,125.53 612,271 612,332.14 698.8,418.94 698.8,615.8 v1(715,632)
SPI0_MOSI: J1.18 U4.62 | length 725
  Top Layer w6: v1(689,632) 705.34,648.34 U4.62
  Bottom Layer w6: J1.18@435.04,55.12 443.85,63.93 443.85,124.85 599,280 599,334.69 687.8,423.49 687.8,630.8 v1(689,632)
SPI1_CLK: J1.19 U4.64 | length 807.9
  Top Layer w6: J1.19 450.79,121.79 526,197 526,632.11 584.01,690.12 618.94,690.12 631.69,702.87 653,702.87 664,691.87 664.19,691.87 673.84,682.22 U4.64
SPI1_CS: J1.23 U4.66 | length 695.1
  Top Layer w6: J1.23 513.78,125.78 548,160 548,623 593.12,668.12 U4.66
SPI1_MISO: J1.17 U4.63 | length 856.3
  Top Layer w6: J1.17 419.29,120.29 515,216 515,639 577.12,701.12 612,701.12 624.75,713.87 657.56,713.87 661.8,709.62 662.18,709.62 689.59,682.22 U4.63
SPI1_MOSI: J1.21 U4.65 | length 761.2
  Top Layer w6: J1.21 482.28,122.28 537,177 537,627.56 588.56,679.12 623.97,679.12 630.41,685.56 630.41,686.03 636.25,691.87 648.44,691.87 658.09,682.22 U4.65
TXD: J1.10 U4.48 U6.9 | length 1835.1
  Top Layer w6: v1(924,635) 925.81,636.81 U4.48 925.81,682.22 937.28,693.68 987.68,693.68 998.68,704.68 U6.9
  Bottom Layer w6: J1.10 183.07,149.37 2,330.44 2,635.56 112.32,745.87 832.13,745.87 886.39,691.62 886.39,672.61 v1(924,635)
USB_ID: R9.2 U4.47 USB1.4 | length 1581.6
  Top Layer w6: USB1.4 124.74,1056.74 183.01,1115.01 986.99,1115.01 1053.33,1048.67 R9.2 1009.9,675.12 979.15,644.37 945.07,644.37 941.56,647.88 U4.47
USB_N: J1.14 U4.68 USB1.2 | length 1626.7
  Top Layer w6: v1(175,1022) 175.46,1021.54 175.46,975.58 USB1.2 ; v1(577,628) 584.13,620.87 U4.68
  Signal & VCC w6: v1(175,1022) 176.87,1020.13 176.87,649.13 198,628 v1(577,628)
  Bottom Layer w6: J1.14 246.06,382.61 491.45,628 v1(577,628)
USB_P: J1.16 U4.69 USB1.3 | length 1671.1
  Top Layer w6: USB1.3 150.67,975.45 150.67,1046.67 v1(151,1047) ; v1@568,607 v1(570,607) 570.94,606.06 609.91,606.06 U4.69
  Signal & VCC w6: v1(151,1047) 151,939.83 145.13,933.96 145.13,665.32 203.44,607 v1(570,607)
  Bottom Layer w6: J1.16@277.56,55.12 277.56,398.55 486.01,607 v1(570,607)
pads on no net: J1.5 J1.6 J1.7 J1.8 U4.72 U4.75 U4.76 U4.77 U4.78 U4.79 U4.84 U4.85 U4.86 U6.4 U6.5 U6.6 USB2.4

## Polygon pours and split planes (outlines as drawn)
GND on GND (split plane): 1076.36,146.08 1043.31,146.08 1042.94,146.04 1037.53,145.74 1031.83,144.77 1026.27,143.17 1020.93,140.96 1015.87,138.16 1011.15,134.81 1006.84,130.96 1002.98,126.65 999.64,121.93 996.84,116.87 994.62,111.52 993.02,105.97 992.05,100.26 991.75,94.86 991.71,94.49 991.71,20.1 403.96,20.1 403.96,127.95 403.91,128.4 403.62,133.51 402.69,138.99 401.15,144.34 399.02,149.48 396.33,154.34 393.11,158.88 389.41,163.03 385.26,166.74 380.72,169.95 375.85,172.65 370.71,174.77 365.37,176.31 359.88,177.25 354.33,177.56 348.78,177.25 343.29,176.31 337.95,174.77 332.81,172.65 327.94,169.95 323.4,166.74 319.25,163.03 315.55,158.88 312.33,154.34 309.64,149.48 307.51,144.34 305.97,138.99 305.04,133.51 304.75,128.4 304.71,127.95 304.71,20.1 20.1,20.1 20.1,94.49 20.06,94.86 19.76,100.26 18.79,105.97 17.19,111.52 14.97,116.87 12.18,121.93 8.83,126.65 4.97,130.96 0.66,134.81 -4.06,138.16 -9.12,140.96 -14.46,143.17 -20.02,144.77 -25.72,145.74 -31.13,146.04 -31.5,146.08 -64.55,146.08 -64.55,1113.05 1076.36,1113.05

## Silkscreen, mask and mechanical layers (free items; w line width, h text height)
Mechanical 1:
  lines w10: -84.65,200.79 -84.65,1133.14 1096.46,1133.14 ; 1096.46,200.79 1096.46,1131.99 ; -2415.67,-819.88 -2415.67,3180.12 3584.33,3180.12 3584.33,-819.88 -2415.67,-819.88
